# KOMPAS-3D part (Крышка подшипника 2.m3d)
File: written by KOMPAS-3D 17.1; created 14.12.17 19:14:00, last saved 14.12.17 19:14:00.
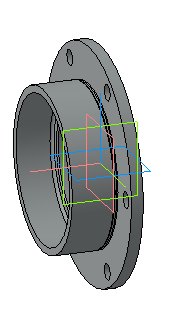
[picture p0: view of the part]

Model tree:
1. Операция без истории:1  (labels: Крышка подшипника 2)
